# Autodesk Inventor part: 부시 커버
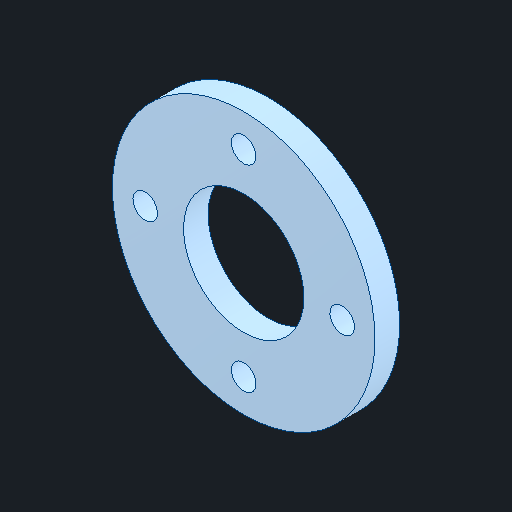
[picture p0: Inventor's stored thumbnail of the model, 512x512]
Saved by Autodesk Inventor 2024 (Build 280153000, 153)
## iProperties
Created: 2024-05
Part Number: 부시 커버
Material: 강철, 연강
Document SubType Name: Modeling
Designer: kh_501
Density: 7.85 g/cm^3
Appearance: 기본값
Author: jhkim
Sending System: Autodesk Inventor 2025
Preprocessor: ST-DEVELOPER v20
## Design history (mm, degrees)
node "부시 커버1"
node "솔리드2"
node "솔리드1"
